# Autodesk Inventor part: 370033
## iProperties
Company: Mayer & Müller AG Schaltgeräte
Created: 2006-03
Part Number: 370033
Material: 1.0718
Document SubType Name: Modeling
Designer: I.Baliuc
Manufacturer: Standard
Standards Organization: Custom
Description: Lochbandklemme
Density: 7.86 g/cm^3
Author: T.Messerschmitt
Revision Number: 370033
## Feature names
1. Extrusion1
2. Rundung1 [Fillet]
3. Extrusion2
